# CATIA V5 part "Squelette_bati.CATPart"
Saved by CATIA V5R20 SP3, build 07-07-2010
Part number: Squelette_Bati
Publications: "Plan.1", "Droite.1", "Point.4", "Point.5", "Plan.4", "Plan.5", "Droite.2", "Plan.6", "Point.6", "Droite.3"
Bounding box of the stored display mesh (mm): x -10 to 10, y 0 to 58, z -10 to 10
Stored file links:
  C:\Documents and Settings\Propriétaire\Mes documents\IFMA\COURS\PROJ IAO\CATIA\Squelette_bati.CATPart
  C:\Documents and Settings\Propriétaire\Mes documents\IFMA\COURS\PROJ IAO\CATIA\Assemblage Squelette.CATProduct
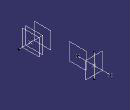
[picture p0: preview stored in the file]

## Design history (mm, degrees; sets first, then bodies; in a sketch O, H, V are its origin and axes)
Set1
  Point1: linked copy from another document
Set2
  Plane1: type Offset, RefPlane yz-plane, Offset 0
  Line1: type Normal, RefPoint Point1, RefSkin Plane1, Start -10, End 10
  Point2: type OnPlane, Support Plane2, H 30, V 0, Direction (0, 1, 0)
  Point3: type OnPlane, Support Plane2, H 58, V 0, Direction (0, 1, 0)
  Plane2: type Offset, RefPlane Plane1, Offset 10, reversed
  Plane3: type Offset, RefPlane Plane1, Offset 3, reversed
  Plane4: type OffsetPt, RefPlane Plane2, RefPoint Point2
  Line2: type PtPt, FirstPoint Point3, SecondPoint Point2
  Point4: type OnCurve, Support Line2, Length 14
  Line3: type Angle, RefPoint Point4, Curve Line2, Support Plane4, Start -10, End 10, Angle 90
  Plane5: type Angle, RefPlane Plane4, Direction Line3, Angle 90
Body1 (main body)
